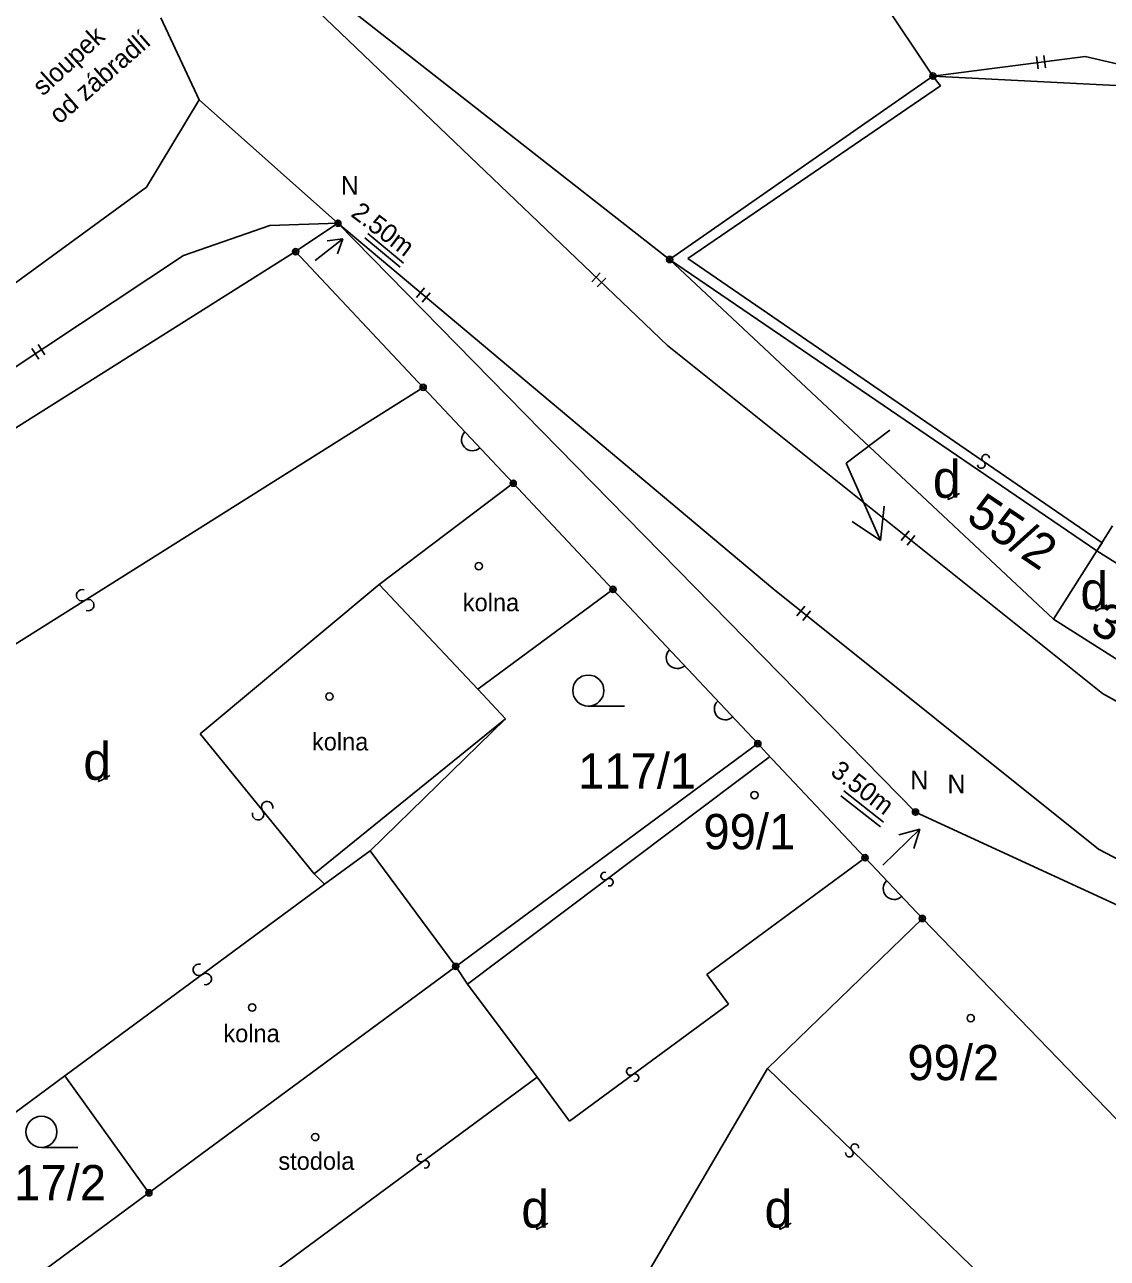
# Model space of a CAD drawing. Extents: x -815878 to -812162, y -1076286 to -1072327.
# Drawn here: x -813629.7 to -813577.5, y -1074235.6 to -1074176.2 of the extents above; entities that cross this region are included whole.
import ezdxf

# ---------------------------------------------------------------- set-up
doc = ezdxf.new("R2010")
doc.units = 0
for name, color, linetype in [('Vrstva 1', 7, 'Continuous'), ('Vrstva 18', 7, 'Continuous'), ('Vrstva 19', 7, 'Continuous'), ('Vrstva 24', 7, 'Continuous'), ('Vrstva 25', 7, 'Continuous'), ('Vrstva 4', 7, 'Continuous'), ('Vrstva 56', 7, 'Continuous'), ('Vrstva 62', 7, 'Continuous'), ('Vrstva 63', 7, 'Continuous')]:
    doc.layers.add(name, color=color, linetype=linetype)

msp = doc.modelspace()

# ---------------------------------------------------------------- linework, layer by layer
at = {"layer": 'Vrstva 1'}
for p, q in [((-813617.72, -1074172.51), (-813598.59, -1074187.5)), ((-813589.7, -1074172.97), (-813585.9, -1074178.66)), ((-813623.12, -1074175.85), (-813621.27, -1074179.8)), ((-813585.9, -1074178.66), (-813578.57, -1074177.72)), ((-813578.57, -1074177.72), (-813571.14, -1074179.41)), ((-813598.59, -1074187.5), (-813585.9, -1074178.66)), ((-813585.9, -1074178.66), (-813571.14, -1074179.41)), ((-813621.27, -1074179.8), (-813623.8, -1074184.01)), ((-813621.27, -1074179.8), (-813614.58, -1074185.75)), ((-813623.8, -1074184.01), (-813630.6, -1074188.97)), ((-813616.62, -1074187.12), (-813614.58, -1074185.75)), ((-813586.74, -1074214.13), (-813614.58, -1074185.75)), ((-813616.62, -1074187.12), (-813645.92, -1074205.56)), ((-813610.47, -1074193.66), (-813616.62, -1074187.12)), ((-813598.59, -1074187.5), (-813578, -1074201.54)), ((-813580.09, -1074204.84), (-813598.59, -1074187.5)), ((-813606.13, -1074198.28), (-813610.47, -1074193.66)), ((-813601.32, -1074203.4), (-813606.13, -1074198.28)), ((-813578, -1074201.54), (-813577.24, -1074200.33)), ((-813579.56, -1074204), (-813578, -1074201.54)), ((-813578, -1074201.54), (-813572.53, -1074205)), ((-813607.84, -1074208.21), (-813601.32, -1074203.4)), ((-813594.34, -1074210.83), (-813601.32, -1074203.4)), ((-813580.09, -1074204.84), (-813579.56, -1074204)), ((-813574.62, -1074208.3), (-813580.09, -1074204.84)), ((-813606.5, -1074209.64), (-813607.84, -1074208.21)), ((-813606.5, -1074209.64), (-813613.02, -1074215.99)), ((-813608.9, -1074221.57), (-813594.34, -1074210.83)), ((-813593.9, -1074211.3), (-813594.34, -1074210.83)), ((-813589.17, -1074216.33), (-813593.9, -1074211.3)), ((-813586.74, -1074214.13), (-813566.74, -1074223.36)), ((-813613.02, -1074215.99), (-813608.9, -1074221.57)), ((-813586.41, -1074219.26), (-813589.17, -1074216.33)), ((-813593.88, -1074226.48), (-813586.41, -1074219.26)), ((-813574.11, -1074231.99), (-813586.41, -1074219.26)), ((-813623.69, -1074232.48), (-813608.9, -1074221.57)), ((-813593.88, -1074226.48), (-813599.76, -1074236.52)), ((-813634.31, -1074231.69), (-813627.74, -1074226.84)), ((-813627.74, -1074226.84), (-813623.69, -1074232.48)), ((-813630.26, -1074237.33), (-813623.69, -1074232.48))]:
    msp.add_line(p, q, dxfattribs=at)
at = {"layer": 'Vrstva 24'}
for centre, radius in [((-813585.9, -1074178.66), 0.15), ((-813585.9, -1074178.66), 0.075), ((-813614.58, -1074185.75), 0.15), ((-813614.58, -1074185.75), 0.075), ((-813616.62, -1074187.12), 0.15), ((-813616.62, -1074187.12), 0.075), ((-813598.59, -1074187.5), 0.15), ((-813598.59, -1074187.5), 0.075), ((-813610.47, -1074193.66), 0.15), ((-813610.47, -1074193.66), 0.075), ((-813606.13, -1074198.28), 0.15), ((-813606.13, -1074198.28), 0.075), ((-813601.32, -1074203.4), 0.15), ((-813601.32, -1074203.4), 0.075), ((-813594.34, -1074210.83), 0.15), ((-813594.34, -1074210.83), 0.075), ((-813586.74, -1074214.13), 0.15), ((-813586.74, -1074214.13), 0.075), ((-813589.17, -1074216.33), 0.15), ((-813589.17, -1074216.33), 0.075), ((-813586.41, -1074219.26), 0.15), ((-813586.41, -1074219.26), 0.075), ((-813608.9, -1074221.57), 0.15), ((-813608.9, -1074221.57), 0.075), ((-813623.69, -1074232.48), 0.15), ((-813623.69, -1074232.48), 0.075)]:
    msp.add_circle(centre, radius, dxfattribs=at)
at = {"layer": 'Vrstva 25'}
for p, q in [((-813600.759, -1074209.025), (-813602.509, -1074209.025)), ((-813627.12, -1074230.29), (-813628.87, -1074230.29))]:
    msp.add_line(p, q, dxfattribs=at)
for centre, radius in [((-813607.79, -1074202.28), 0.175), ((-813602.509, -1074208.275), 0.75), ((-813614.99, -1074208.56), 0.175), ((-813594.5, -1074213.31), 0.175), ((-813618.71, -1074223.55), 0.175), ((-813584.08, -1074224.06), 0.175), ((-813628.87, -1074229.54), 0.75), ((-813615.67, -1074229.79), 0.175)]:
    msp.add_circle(centre, radius, dxfattribs=at)
for points in [[(-813585.152, -1074198.983), (-813585.152, -1074199), (-813585.191, -1074199.108), (-813584.621, -1074198.771)], [(-813578.042, -1074204.353), (-813578.042, -1074204.37), (-813578.081, -1074204.478), (-813577.511, -1074204.141)], [(-813626.099, -1074212.573), (-813626.099, -1074212.59), (-813626.138, -1074212.698), (-813625.568, -1074212.361)], [(-813604.988, -1074234.153), (-813604.988, -1074234.17), (-813605.027, -1074234.278), (-813604.457, -1074233.941)], [(-813593.268, -1074234.153), (-813593.268, -1074234.17), (-813593.307, -1074234.278), (-813592.737, -1074233.941)]]:
    msp.add_open_spline(points, degree=2, dxfattribs=at)
at = {"layer": 'Vrstva 4'}
for p, q in [((-813598.7, -1074191.65), (-813618.14, -1074173.04)), ((-813585.54, -1074179.13), (-813597.71, -1074187.45)), ((-813585.9, -1074178.66), (-813585.54, -1074179.13)), ((-813617.86, -1074185.86), (-813614.58, -1074185.75)), ((-813593.62, -1074203.36), (-813614.58, -1074185.75)), ((-813622.02, -1074187.3), (-813617.86, -1074185.86)), ((-813630.33, -1074192.82), (-813622.02, -1074187.3)), ((-813597.71, -1074187.45), (-813577.74, -1074201.16)), ((-813577.72, -1074208.41), (-813598.7, -1074191.65)), ((-813641.22, -1074213.02), (-813610.47, -1074193.66)), ((-813606.13, -1074198.28), (-813612.59, -1074203.16)), ((-813577.74, -1074201.16), (-813578, -1074201.54)), ((-813612.59, -1074203.16), (-813621.22, -1074210.36)), ((-813612.59, -1074203.16), (-813607.84, -1074208.21)), ((-813577.92, -1074215.91), (-813593.62, -1074203.36)), ((-813568.57, -1074213.6), (-813577.72, -1074208.41)), ((-813606.5, -1074209.64), (-813615.73, -1074217.11)), ((-813615.73, -1074217.11), (-813621.22, -1074210.36)), ((-813593.8, -1074211.48), (-813608.33, -1074222.42)), ((-813615.23, -1074217.61), (-813613.02, -1074215.99)), ((-813571.17, -1074219.49), (-813577.92, -1074215.91)), ((-813589.17, -1074216.33), (-813596.8, -1074221.96)), ((-813615.23, -1074217.61), (-813615.73, -1074217.11)), ((-813627.74, -1074226.84), (-813615.23, -1074217.61)), ((-813608.9, -1074221.57), (-813608.33, -1074222.42)), ((-813596.8, -1074221.96), (-813595.76, -1074223.38)), ((-813608.33, -1074222.42), (-813604.98, -1074226.9)), ((-813595.76, -1074223.38), (-813603.41, -1074229.02)), ((-813579.68, -1074240.23), (-813593.88, -1074226.48)), ((-813625.87, -1074242.31), (-813604.98, -1074226.9)), ((-813603.41, -1074229.02), (-813604.98, -1074226.9))]:
    msp.add_line(p, q, dxfattribs=at)
at = {"layer": 'Vrstva 62'}
for p, q in [((-813580.833, -1074178.313), (-813580.909, -1074177.717)), ((-813580.476, -1074178.267), (-813580.552, -1074177.672)), ((-813601.931, -1074188.142), (-813602.346, -1074188.575)), ((-813601.671, -1074188.391), (-813602.086, -1074188.824)), ((-813610.4, -1074188.87), (-813610.786, -1074189.329)), ((-813610.125, -1074189.101), (-813610.511, -1074189.561)), ((-813628.697, -1074192.096), (-813629.029, -1074191.596)), ((-813628.997, -1074192.295), (-813629.329, -1074191.795)), ((-813587.052, -1074200.571), (-813587.426, -1074201.04)), ((-813586.77, -1074200.796), (-813587.145, -1074201.265)), ((-813592.081, -1074204.206), (-813592.456, -1074204.675)), ((-813591.8, -1074204.431), (-813592.175, -1074204.899))]:
    msp.add_line(p, q, dxfattribs=at)
for centre, radius, start, end in [((-813608.096, -1074196.188), 0.525, 133.45611, 312.96407), ((-813583.362, -1074197.077), 0.184, 2.68752, 235.27752), ((-813583.572, -1074197.38), 0.184, 182.90197, 54.99997), ((-813626.906, -1074203.682), 0.276, 69.35253, 301.94253), ((-813626.615, -1074204.152), 0.277, 249.56698, 121.66498), ((-813598.23, -1074206.69), 0.525, 133.45735, 312.96531), ((-813595.91, -1074209.159), 0.525, 133.45735, 312.96531), ((-813617.991, -1074213.891), 0.277, 346.49534, 218.59334), ((-813618.423, -1074214.237), 0.276, 166.28089, 38.87089), ((-813601.72, -1074217.212), 0.184, 74.34974, 306.44773), ((-813601.5, -1074217.508), 0.184, 254.13528, 126.72528), ((-813587.77, -1074217.817), 0.525, 133.53471, 313.04266), ((-813621.277, -1074221.728), 0.276, 73.57855, 306.16855), ((-813620.951, -1074222.175), 0.277, 253.793, 125.891), ((-813600.48, -1074226.631), 0.184, 73.77241, 305.87041), ((-813600.264, -1074226.929), 0.184, 253.55796, 126.14796), ((-813589.667, -1074230.302), 0.184, 353.29513, 225.39312), ((-813610.584, -1074230.805), 0.184, 73.57349, 306.16349), ((-813610.367, -1074231.103), 0.184, 253.78795, 125.88594), ((-813589.925, -1074230.565), 0.184, 173.08067, 45.67067)]:
    msp.add_arc(centre, radius, start, end, dxfattribs=at)
at = {"layer": 'Vrstva 63'}
for p, q in [((-813613.13, -1074186.25), (-813611.42, -1074187.67)), ((-813615.68, -1074187.54), (-813614.34, -1074186.5)), ((-813614.34, -1074186.5), (-813615.1, -1074186.6)), ((-813614.34, -1074186.5), (-813614.6, -1074187.23)), ((-813613.285, -1074186.453), (-813611.575, -1074187.873)), ((-813587.97, -1074195.72), (-813590.08, -1074197.32)), ((-813590.08, -1074197.32), (-813588.43, -1074201.04)), ((-813588.43, -1074201.04), (-813588.25, -1074199.39)), ((-813588.43, -1074201.04), (-813589.8, -1074200.12)), ((-813590.19, -1074213.11), (-813588.29, -1074214.61)), ((-813590.331, -1074213.344), (-813588.431, -1074214.844)), ((-813588.31, -1074216.69), (-813586.53, -1074214.96)), ((-813586.53, -1074214.96), (-813587.55, -1074215.22)), ((-813586.53, -1074214.96), (-813586.82, -1074215.88))]:
    msp.add_line(p, q, dxfattribs=at)

# ---------------------------------------------------------------- texts
at = {"layer": 'Vrstva 18'}
for s, p in [('117/1', (-813603.004, -1074213)), ('117/2', (-813631.444, -1074232.84))]:
    msp.add_text(s, height=1.7, dxfattribs=at).set_placement(p)
at = {"layer": 'Vrstva 19'}
for s, rotation, p in [('55/2', 326.07028, (-813584.366, -1074200.067)), ('335', 329.73721, (-813578.405, -1074205.374))]:
    msp.add_text(s, height=1.7, rotation=rotation, dxfattribs=at).set_placement(p)
for s, p in [('99/1', (-813596.961, -1074215.92)), ('99/2', (-813587.131, -1074227.05))]:
    msp.add_text(s, height=1.7, dxfattribs=at).set_placement(p)
at = {"layer": 'Vrstva 25'}
for p in [(-813585.903, -1074198.982), (-813578.793, -1074204.352), (-813626.85, -1074212.572), (-813605.739, -1074234.152), (-813594.019, -1074234.152)]:
    msp.add_text('d', height=1.8, dxfattribs=at).set_placement(p)
at = {"layer": 'Vrstva 56'}
for s, rotation, p in [('sloupek', 42.49909, (-813628.796, -1074179.652)), ('od zábradlí', 41.14802, (-813628.008, -1074181.016)), ('2.50m', 322.77402, (-813614.004, -1074185.378)), ('3.50m', 322.77402, (-813590.892, -1074212.293))]:
    msp.add_text(s, height=0.9, rotation=rotation, dxfattribs=at).set_placement(p)
for s, height, p in [('N', 0.9, (-813614.44, -1074184.38)), ('kolna', 0.85, (-813608.56, -1074204.45)), ('kolna', 0.85, (-813615.83, -1074211.16)), ('N', 0.9, (-813586.99, -1074213.04)), ('N', 0.9, (-813585.2, -1074213.22)), ('kolna', 0.85, (-813620.1, -1074225.22)), ('stodola', 0.85, (-813617.45, -1074231.37))]:
    msp.add_text(s, height=height, dxfattribs=at).set_placement(p)

doc.saveas('drawing.dxf')
